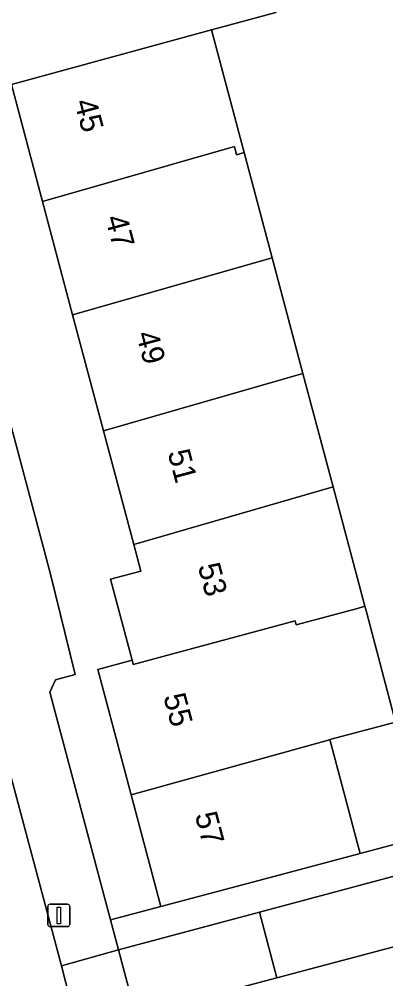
# Model space of a CAD drawing. Extents: x 162542 to 163147, y 380779 to 381521.
# Drawn here: x 162786.35 to 162802.78, y 380876.19 to 380919.18 of the extents above; entities that cross this region are included whole.
import ezdxf

# ---------------------------------------------------------------- set-up
doc = ezdxf.new("R2010")
doc.units = 0
for name, color, linetype in [('IMGEO_Erf', 7, 'Continuous'), ('IMGEO_Lichtmast', 7, 'Continuous'), ('IMGEO_Pand', 7, 'Continuous'), ('IMGEO_Pand_nummerreeks', 7, 'Continuous'), ('IMGEO_Rijbaan_lokaal_open', 7, 'Continuous'), ('IMGEO_Voetpad_open', 7, 'Continuous')]:
    doc.layers.add(name, color=color, linetype=linetype)

msp = doc.modelspace()

# ---------------------------------------------------------------- linework, layer by layer
at = {"layer": 'IMGEO_Erf'}
for points in [[(162806.857, 380927.348), (162796.44, 380924.766), (162797.847, 380919.483), (162794.967, 380918.7), (162796.43, 380913.206), (162797.685, 380908.496), (162799.067, 380903.307), (162800.42, 380898.227), (162801.843, 380892.883), (162801.926, 380892.571), (162803.223, 380887.695), (162800.276, 380886.911), (162800.948, 380884.389), (162801.506, 380882.293), (162801.634, 380881.813), (162815.673, 380885.555)], [(162804.265, 380877.928), (162797.902, 380876.242), (162791.582, 380874.558), (162793.21, 380868.165), (162796.373, 380869.011), (162799.469, 380869.839), (162799.777, 380868.58), (162799.819, 380868.421), (162800.002, 380868.47), (162803.926, 380869.52)]]:
    msp.add_lwpolyline(points, dxfattribs=at)
msp.add_lwpolyline([(162787.389, 380911.023), (162785.994, 380916.261), (162784.652, 380921.296), (162780.832, 380920.278), (162787.754, 380894.316), (162788.858, 380889.82), (162787.979, 380889.585), (162787.726, 380889.027), (162790.444, 380878.831), (162792.701, 380879.433), (162791.368, 380884.436), (162789.872, 380890.054), (162791.407, 380890.462), (162790.439, 380894.095), (162791.801, 380894.457), (162791.485, 380895.645), (162790.126, 380900.745), (162788.743, 380905.938)], close=True, dxfattribs=at)
at = {"layer": 'IMGEO_Lichtmast'}
for p, q in [((162787.626, 380878.631), (162787.626, 380879.431)), ((162787.626, 380879.431), (162787.626, 380878.631)), ((162787.726, 380879.531), (162788.516, 380879.531)), ((162788.516, 380879.531), (162787.726, 380879.531)), ((162788.616, 380879.431), (162788.616, 380878.631)), ((162788.616, 380878.631), (162788.616, 380879.431)), ((162788.516, 380878.531), (162787.726, 380878.531)), ((162787.726, 380878.531), (162788.516, 380878.531))]:
    msp.add_line(p, q, dxfattribs=at)
msp.add_lwpolyline([(162788.046, 380879.406), (162788.196, 380879.406), (162788.196, 380878.656), (162788.046, 380878.656), (162788.046, 380879.406)], dxfattribs=at)
for centre, start, end in [((162787.726, 380879.431), 90, 180), ((162787.726, 380879.431), 90, 180), ((162788.516, 380879.431), 0, 90), ((162788.516, 380879.431), 360, 90), ((162787.726, 380878.631), 180, 270), ((162787.726, 380878.631), 180, 270), ((162788.516, 380878.631), 270, 0), ((162788.516, 380878.631), 270, 0)]:
    msp.add_arc(centre, 0.1, start, end, dxfattribs=at)
at = {"layer": 'IMGEO_Pand'}
for points in [[(162796.44, 380924.766), (162793.556, 380923.998), (162793.626, 380923.737), (162784.64, 380921.342), (162784.652, 380921.296), (162785.994, 380916.261), (162794.967, 380918.7), (162797.847, 380919.483)], [(162794.967, 380918.7), (162785.994, 380916.261), (162787.389, 380911.023), (162795.997, 380913.48), (162796.096, 380913.108), (162796.43, 380913.206)], [(162796.43, 380913.206), (162796.096, 380913.108), (162795.997, 380913.48), (162787.389, 380911.023), (162788.743, 380905.938), (162797.685, 380908.496)], [(162797.685, 380908.496), (162788.743, 380905.938), (162790.126, 380900.745), (162799.067, 380903.307)], [(162800.42, 380898.227), (162799.067, 380903.307), (162790.126, 380900.745), (162791.485, 380895.645)], [(162800.42, 380898.227), (162791.485, 380895.645), (162791.801, 380894.457), (162790.439, 380894.095), (162791.407, 380890.462), (162791.458, 380890.27), (162798.721, 380892.231), (162798.77, 380892.047), (162801.513, 380892.778), (162801.843, 380892.883)], [(162791.368, 380884.436), (162800.15, 380886.87), (162800.276, 380886.911), (162803.223, 380887.695), (162801.926, 380892.571), (162801.843, 380892.883), (162801.513, 380892.778), (162798.77, 380892.047), (162798.721, 380892.231), (162791.458, 380890.27), (162791.407, 380890.462), (162789.872, 380890.054)], [(162800.276, 380886.911), (162800.15, 380886.87), (162791.368, 380884.436), (162792.701, 380879.433), (162797.533, 380880.72), (162801.634, 380881.813), (162801.506, 380882.293), (162800.948, 380884.389)], [(162804.058, 380878.707), (162803.48, 380880.877), (162797.119, 380879.182), (162797.902, 380876.242), (162804.265, 380877.928)], [(162791.582, 380874.558), (162797.902, 380876.242), (162797.119, 380879.182), (162790.799, 380877.498)]]:
    msp.add_lwpolyline(points, close=True, dxfattribs=at)
at = {"layer": 'IMGEO_Rijbaan_lokaal_open'}
msp.add_lwpolyline([(162789.002, 380873.892), (162788.444, 380876.005), (162788.238, 380876.778), (162785.664, 380886.45), (162780.982, 380885.195), (162782.851, 380878.347), (162783.57, 380875.561), (162784.325, 380872.639), (162784.433, 380872.219), (162789.507, 380853.33), (162789.924, 380851.717), (162790.179, 380850.73), (162794.883, 380852.068), (162794.551, 380853.257), (162794.102, 380855.017), (162792.548, 380860.454), (162790.496, 380868.229)], close=True, dxfattribs=at)
at = {"layer": 'IMGEO_Voetpad_open'}
for points in [[(162784.888, 380889.476), (162785.006, 380889.053), (162785.664, 380886.45), (162788.238, 380876.778), (162790.799, 380877.498), (162790.444, 380878.831), (162787.726, 380889.027), (162787.979, 380889.585), (162788.858, 380889.82), (162787.754, 380894.316), (162780.832, 380920.278), (162780.617, 380921.086), (162763.955, 380983.585), (162763.686, 380984.593), (162759.578, 381000), (162755.726, 381014.447), (162754.046, 381014.881), (162751.366, 381025.19), (162751.014, 381026.543), (162750.404, 381028.836), (162749.506, 381032.166), (162746.399, 381043.845)], [(162815.673, 380885.555), (162801.634, 380881.813), (162797.533, 380880.72), (162792.701, 380879.433), (162790.444, 380878.831), (162790.799, 380877.498), (162797.119, 380879.182), (162803.48, 380880.877)]]:
    msp.add_lwpolyline(points, dxfattribs=at)
msp.add_lwpolyline([(162788.238, 380876.778), (162788.444, 380876.005), (162789.002, 380873.892), (162791.582, 380874.558), (162790.799, 380877.498)], close=True, dxfattribs=at)

# ---------------------------------------------------------------- texts
at = {"layer": 'IMGEO_Pand_nummerreeks'}
for s, rotation, p in [('45', 284.9143, (162788.81, 380915.478)), ('47', 284.9143, (162790.194, 380910.28)), ('49', 284.9143, (162791.579, 380905.081)), ('51', 284.9143, (162792.994, 380899.773)), ('53', 284.9143, (162794.348, 380894.684)), ('55', 284.915, (162792.802, 380888.846)), ('57', 284.9139, (162794.215, 380883.536))]:
    msp.add_text(s, height=1, rotation=rotation, dxfattribs=at).set_placement(p)

doc.saveas('drawing.dxf')
